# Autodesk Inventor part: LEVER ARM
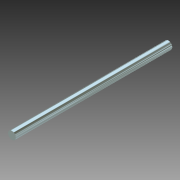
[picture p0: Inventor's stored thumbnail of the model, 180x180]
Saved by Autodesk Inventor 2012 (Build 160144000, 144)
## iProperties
Shininess: 64.0
Length Units: 11272
Angle Units: 11279
Time Units: 11290
Mass Units: 11286
Length Display Precision: 3
Angle Display Precision: 2
Compacted: True
Part Number: LEVER ARM
Document SubType Name: Modeling
Created: 2003-11
Designer: Autodesk, Inc.
Manufacturer: Standard
Standards Organization: Custom
Mass: 252.903 g
Surface Area: 103.875 cm^2
Volume: 32.1759 cm^3
Density: 7.86 g/cm^3
Material: Steel, Mild
Density: 0.0
Volumn: 0.0
Area: 0.0
PropertySet Name: Model Information
Control State: 0
Master: False
Checked Out: False
Author: Autodesk, Inc.
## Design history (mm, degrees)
sketch "Sketch1"
  geometry: C1 r 6.35 at (0, 0); 1 further point
  constraints: 1 centre point, 1 coincident
  dimensions: "d0" = 12.7 diameter of C1
extrude "Extrusion1" new body sketch "Sketch1" distance "d1" = 254; taper "d2" = 0 deg
workplane "Work Plane1"
body "Solid1"
